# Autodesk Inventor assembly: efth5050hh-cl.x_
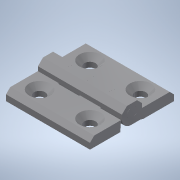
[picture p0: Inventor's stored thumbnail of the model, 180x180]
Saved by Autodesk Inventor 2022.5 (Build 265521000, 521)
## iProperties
Part Number: efth5050hh-cl.x_
Material: 一般
Document SubType Name: Assembly
Designer: ImaoCorp
Sending System: SOLIDWORKS 2017-2017317
MC: AMD64
MC_MODEL: Intel64 Family 6 Model 60 Stepping 3, GenuineIntel
OS: Windows_NT
FRU: Parasolid Version 29.0, build 201,  4-17-2017
FORMAT: text
GUISE: transmit
KEY: efth5050hh-cl
FILE: efth5050hh-cl.x_t
DATE: Mon May 13 14:22:14 2019
Author: ImaoCorp
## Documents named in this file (4)
- X:\14_SW2022-Inv2022\00_全2023-1023新製品(TCC)まで\e\efth5050hh-cl\EFTH5050HH-CL.iam
- X:\14_SW2022-Inv2022\00_全2023-1023新製品(TCC)まで\e\efth5050hh-cl\efth5050hh-cl_01.ipt
- X:\14_SW2022-Inv2022\00_全2023-1023新製品(TCC)まで\e\efth5050hh-cl\efth5050hh-cl_02.ipt
- X:\14_SW2022-Inv2022\00_全2023-1023新製品(TCC)まで\e\efth5050hh-cl\efth5050hh-cl_03.ipt
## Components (3 placed, 3 different names)
1. efth5050hh-cl_01
2. efth5050hh-cl_02
3. efth5050hh-cl_03
